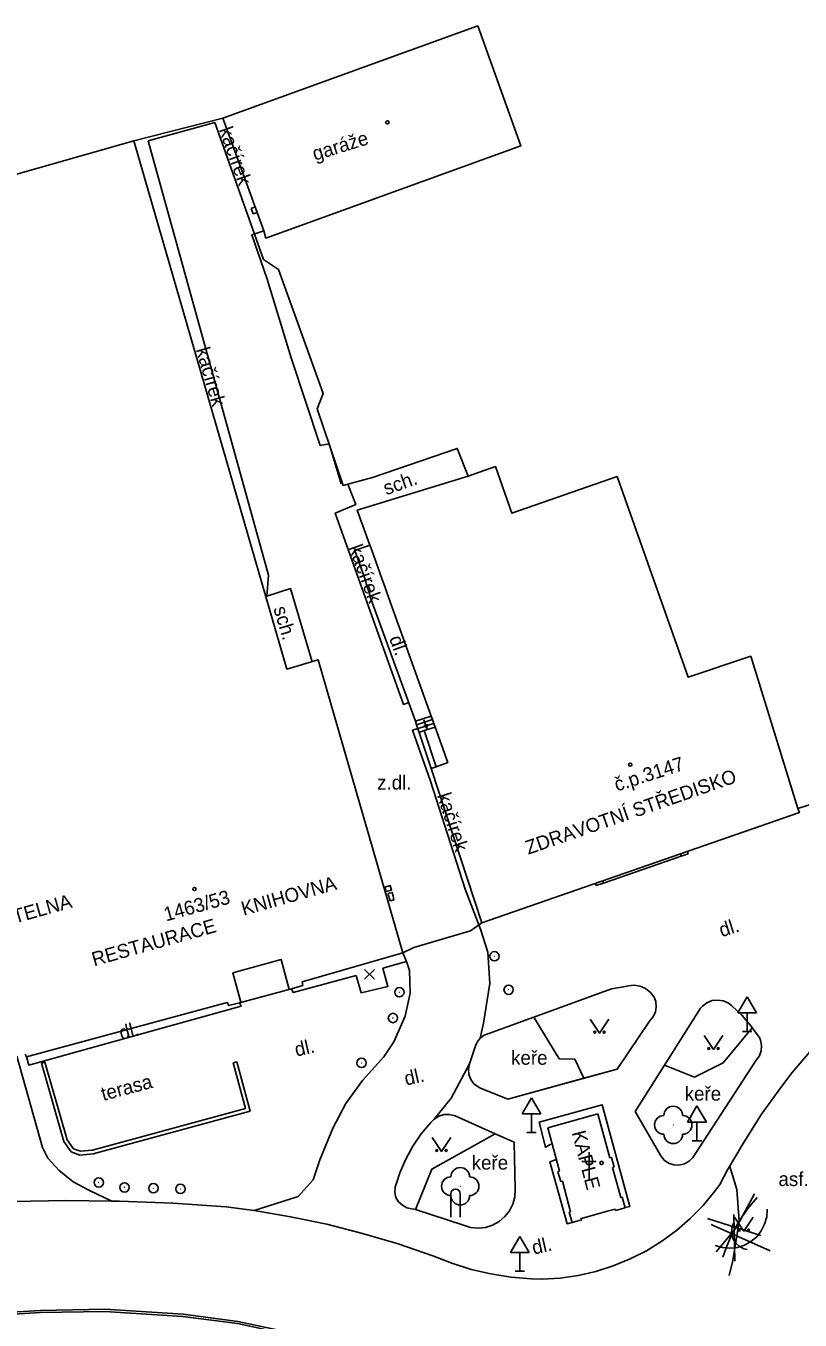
# Model space of a CAD drawing. Extents: x -584400 to -581602, y -1210894 to -1208793.
# Drawn here: x -582919.8 to -582878.3, y -1209481.4 to -1209412.1 of the extents above; entities that cross this region are included whole.
import ezdxf

# ---------------------------------------------------------------- set-up
doc = ezdxf.new("R2010")
doc.units = 0
for name, color, linetype in [('BUDOVY_MĚŘ', 7, 'Continuous'), ('BUDOVY_NEMĚŘ', 7, 'Continuous'), ('OBVOD_PILÍŘE', 7, 'Continuous'), ('POMOC_POPIS', 7, 'Continuous'), ('ROZHRANÍ_PLOCH', 7, 'Continuous'), ('ZELEŇ', 7, 'Continuous'), ('ZN_BUDOV', 7, 'Continuous'), ('ZN_DOPLŇKOVÉ', 7, 'Continuous'), ('ZN_KULTUR', 7, 'Continuous'), ('Č_POPIS_ORIENT', 7, 'Continuous')]:
    doc.layers.add(name, color=color, linetype=linetype)

msp = doc.modelspace()

# ---------------------------------------------------------------- linework, layer by layer
at = {"layer": 'BUDOVY_MĚŘ'}
for points in [[(-582895.57, -1209412.13), (-582909.22, -1209417.06), (-582907.02, -1209423.09), (-582906.91, -1209423.48), (-582893.26, -1209418.55), (-582895.57, -1209412.13)], [(-582913.98, -1209418.28), (-582905.79, -1209446.54), (-582904.11, -1209446.05), (-582899.58, -1209461.71)], [(-582878.44, -1209453.99), (-582878.36, -1209454.21), (-582895.35, -1209460.11), (-582898.06, -1209451.85), (-582897.8, -1209451.76), (-582897.18, -1209451.53), (-582897.86, -1209449.64), (-582897.93, -1209449.44), (-582898, -1209449.24), (-582898.07, -1209449.05), (-582900.42, -1209442.49), (-582900.55, -1209442.12), (-582900.69, -1209441.75), (-582900.82, -1209441.38), (-582901.25, -1209440.18), (-582901.35, -1209439.91), (-582902.02, -1209438.04), (-582896.08, -1209436.22)], [(-582898.06, -1209451.85), (-582897.8, -1209451.76)], [(-582888.84, -1209457.98), (-582884.69, -1209456.54)], [(-582919.72, -1209467.28), (-582908.99, -1209464.37), (-582908.9, -1209464.54), (-582908.32, -1209464.38), (-582905.54, -1209463.64), (-582904.93, -1209463.46), (-582904.97, -1209463.27), (-582899.58, -1209461.71)], [(-582908.25, -1209464.36), (-582908.68, -1209462.78), (-582906.1, -1209462.07), (-582905.67, -1209463.67)], [(-582891.82, -1209471.07), (-582889.15, -1209470.33)], [(-582889.15, -1209470.33), (-582888.5, -1209472.68)], [(-582891.2, -1209473.4), (-582891.82, -1209471.07)], [(-582888.5, -1209472.68), (-582888.42, -1209472.66)], [(-582888.42, -1209472.66), (-582888.28, -1209473.18)], [(-582888.36, -1209473.2), (-582888.28, -1209473.18)], [(-582888.36, -1209473.2), (-582887.91, -1209474.81)], [(-582891.2, -1209473.4), (-582891.28, -1209473.43)], [(-582891.12, -1209473.95), (-582891.28, -1209473.43)], [(-582891.04, -1209473.92), (-582891.12, -1209473.95)], [(-582890.61, -1209475.57), (-582891.04, -1209473.92)], [(-582887.69, -1209475.36), (-582888.2, -1209475.5)], [(-582887.91, -1209474.81), (-582887.84, -1209474.79)], [(-582887.84, -1209474.79), (-582887.69, -1209475.36)], [(-582890.61, -1209475.57), (-582890.69, -1209475.59)], [(-582889.7, -1209475.83), (-582890.04, -1209475.92), (-582890.02, -1209476), (-582890.53, -1209476.14), (-582890.69, -1209475.59)], [(-582890.04, -1209475.92), (-582890.02, -1209476)], [(-582888.22, -1209475.42), (-582888.64, -1209475.53)], [(-582888.22, -1209475.42), (-582888.2, -1209475.5)]]:
    msp.add_lwpolyline(points, dxfattribs=at)
at = {"layer": 'BUDOVY_NEMĚŘ'}
for points in [[(-582913.98, -1209418.28), (-582931.99, -1209423.39), (-582927.85, -1209438.02), (-582922.91, -1209455.53)], [(-582896.08, -1209436.22), (-582894.63, -1209435.7), (-582893.75, -1209438.2), (-582888.12, -1209436.24), (-582884.31, -1209446.97), (-582880.96, -1209445.85), (-582878.44, -1209453.99)], [(-582919.8, -1209467.13), (-582919.72, -1209467.28)]]:
    msp.add_lwpolyline(points, dxfattribs=at)
at = {"layer": 'OBVOD_PILÍŘE'}
for points in [[(-582907.49, -1209421.81), (-582907.7, -1209421.89)], [(-582907.7, -1209421.89), (-582907.65, -1209422.04)], [(-582907.65, -1209422.04), (-582907.59, -1209422.19)], [(-582907.38, -1209422.11), (-582907.49, -1209421.81)], [(-582907.59, -1209422.19), (-582907.38, -1209422.11)], [(-582900.47, -1209458.44), (-582900.54, -1209458.2), (-582900.26, -1209458.12), (-582900.22, -1209458.24), (-582900.19, -1209458.36), (-582900.47, -1209458.44)], [(-582900.38, -1209458.54), (-582900.16, -1209458.48), (-582900.11, -1209458.68), (-582900.06, -1209458.88), (-582900.27, -1209458.93), (-582900.38, -1209458.54)]]:
    msp.add_lwpolyline(points, dxfattribs=at)
at = {"layer": 'ROZHRANÍ_PLOCH'}
for points in [[(-582913.21, -1209418.27), (-582909.65, -1209417.3), (-582907.04, -1209424.62), (-582906.23, -1209425.16), (-582903.84, -1209431.79), (-582904.17, -1209432.61), (-582902.78, -1209436.71), (-582902.53, -1209436.64), (-582902.1, -1209437.74), (-582903.2, -1209438.2), (-582899.55, -1209448.43), (-582899.27, -1209448.33)], [(-582913.21, -1209418.27), (-582906.77, -1209441.51), (-582906.86, -1209442.63), (-582905.59, -1209442.23), (-582904.43, -1209446.14)], [(-582901.35, -1209439.91), (-582902.16, -1209440.19), (-582901.64, -1209441.64)], [(-582901.64, -1209441.64), (-582901.53, -1209442.01)], [(-582901.53, -1209442.01), (-582901.41, -1209442.39)], [(-582901.41, -1209442.39), (-582901.3, -1209442.77)], [(-582901.3, -1209442.77), (-582898.91, -1209449.32)], [(-582898.07, -1209449.05), (-582898.91, -1209449.32), (-582898.85, -1209449.52)], [(-582898.78, -1209449.72), (-582899.06, -1209449.8), (-582898.11, -1209452.54), (-582896.25, -1209458.3), (-582895.42, -1209460.45)], [(-582898.85, -1209449.52), (-582898.42, -1209449.38)], [(-582898.85, -1209449.52), (-582898.78, -1209449.72)], [(-582898.78, -1209449.72), (-582898.41, -1209449.6)], [(-582898.78, -1209449.72), (-582898.71, -1209449.92)], [(-582898.46, -1209449.25), (-582898.42, -1209449.38)], [(-582898.41, -1209449.6), (-582898.46, -1209449.55)], [(-582898.45, -1209449.83), (-582897.86, -1209449.64)], [(-582898.42, -1209449.38), (-582898, -1209449.24)], [(-582898.42, -1209449.38), (-582898.35, -1209449.58)], [(-582898.41, -1209449.6), (-582898.35, -1209449.58)], [(-582898.3, -1209449.71), (-582898.41, -1209449.6)], [(-582898.35, -1209449.58), (-582898.29, -1209449.56)], [(-582898.35, -1209449.58), (-582898.3, -1209449.71)], [(-582898.3, -1209449.71), (-582898.29, -1209449.56)], [(-582898.29, -1209449.56), (-582897.93, -1209449.44)], [(-582898.29, -1209449.56), (-582898.28, -1209449.49)], [(-582898.71, -1209449.92), (-582898.45, -1209449.83)], [(-582898.71, -1209449.92), (-582898.06, -1209451.85)], [(-582898.45, -1209449.83), (-582897.8, -1209451.76)], [(-582884.69, -1209456.54), (-582884.73, -1209456.42)], [(-582884.69, -1209456.54), (-582884.31, -1209456.41)], [(-582884.35, -1209456.29), (-582884.31, -1209456.41)], [(-582889.27, -1209458), (-582889.23, -1209458.11)], [(-582889.23, -1209458.11), (-582888.84, -1209457.98)], [(-582888.84, -1209457.98), (-582888.88, -1209457.86)], [(-582895.42, -1209460.45), (-582895.04, -1209461.67), (-582894.93, -1209463.36), (-582895.26, -1209465.48), (-582895.45, -1209466.28)], [(-582899.39, -1209462.17), (-582899.22, -1209462.66), (-582899.19, -1209463.87), (-582899.46, -1209465.11), (-582900.07, -1209466.48), (-582900.61, -1209467.27), (-582901.75, -1209468.55), (-582902.64, -1209469.77), (-582903.32, -1209471.06), (-582904.02, -1209472.79), (-582904.39, -1209473.86), (-582905.18, -1209474.75), (-582907.54, -1209475.5)], [(-582899.58, -1209461.71), (-582899.39, -1209462.17), (-582900.65, -1209462.53)], [(-582900.65, -1209462.53), (-582900.38, -1209463.51), (-582901.81, -1209463.85), (-582902.08, -1209462.93)], [(-582902.08, -1209462.93), (-582905.46, -1209463.83), (-582905.54, -1209463.64)], [(-582892.58, -1209465.16), (-582888.41, -1209463.64), (-582887.67, -1209463.52)], [(-582886.13, -1209464.08), (-582886.33, -1209463.83), (-582886.59, -1209463.63), (-582886.88, -1209463.5), (-582887.2, -1209463.45), (-582887.52, -1209463.48), (-582887.67, -1209463.52)], [(-582886.39, -1209465.37), (-582886.2, -1209465.15), (-582886.07, -1209464.89), (-582886.02, -1209464.6), (-582886.04, -1209464.31), (-582886.13, -1209464.08)], [(-582880.88, -1209465.72), (-582880.94, -1209465.63), (-582881.44, -1209465.05), (-582882, -1209464.54), (-582882.15, -1209464.41), (-582882.43, -1209464.29), (-582882.73, -1209464.24), (-582883.03, -1209464.27), (-582883.31, -1209464.38), (-582883.55, -1209464.56), (-582883.66, -1209464.68)], [(-582919.72, -1209467.28), (-582919.6, -1209467.72), (-582908.24, -1209464.57), (-582908.32, -1209464.38)], [(-582885.58, -1209467.72), (-582883.66, -1209464.68)], [(-582894.98, -1209466.03), (-582892.58, -1209465.16)], [(-582888.11, -1209467.93), (-582886.39, -1209465.37)], [(-582876.15, -1209465.24), (-582876.58, -1209465.7), (-582877.69, -1209466.89), (-582878.74, -1209468.12), (-582879.36, -1209468.92), (-582880.38, -1209470.35), (-582881.32, -1209471.82), (-582882.2, -1209473.33), (-582882.62, -1209474.1)], [(-582894.98, -1209466.03), (-582895.23, -1209466.12), (-582895.45, -1209466.28), (-582895.61, -1209466.5), (-582895.69, -1209466.69)], [(-582887.15, -1209470.2), (-582885.78, -1209472.58), (-582885.6, -1209472.8), (-582885.36, -1209472.97), (-582885.08, -1209473.06), (-582884.79, -1209473.07), (-582884.51, -1209473), (-582884.26, -1209472.86), (-582884.06, -1209472.66), (-582883.96, -1209472.51), (-582880.67, -1209467.46), (-582880.5, -1209467.23), (-582880.4, -1209466.96), (-582880.38, -1209466.67), (-582880.44, -1209466.39), (-582880.5, -1209466.25), (-582880.88, -1209465.72)], [(-582895.69, -1209466.69), (-582896.01, -1209467.66)], [(-582915.16, -1209475), (-582916.35, -1209474.43), (-582917.22, -1209473.97), (-582917.98, -1209473.36), (-582918.58, -1209472.7), (-582918.87, -1209472.13), (-582920.24, -1209467.25)], [(-582918.93, -1209467.62), (-582918.74, -1209467.57), (-582917.55, -1209471.72), (-582917.21, -1209472.19), (-582916.84, -1209472.33), (-582916.19, -1209472.27), (-582908.01, -1209470.05), (-582908.66, -1209467.6), (-582908.47, -1209467.55)], [(-582918.93, -1209467.62), (-582917.73, -1209471.81), (-582917.34, -1209472.36), (-582916.87, -1209472.53), (-582916.15, -1209472.47), (-582907.76, -1209470.19), (-582908.47, -1209467.55)], [(-582896.01, -1209467.66), (-582896.99, -1209469.48), (-582897.91, -1209470.61)], [(-582896.01, -1209467.66), (-582896.07, -1209467.94), (-582896.05, -1209468.22), (-582895.95, -1209468.49), (-582895.78, -1209468.72), (-582895.55, -1209468.89), (-582895.42, -1209468.95)], [(-582887.15, -1209470.2), (-582885.58, -1209467.72)], [(-582889.89, -1209468.42), (-582893.96, -1209469.55), (-582895.42, -1209468.95)], [(-582888.11, -1209467.93), (-582893.96, -1209469.55)], [(-582888.11, -1209467.93), (-582889.89, -1209468.42)], [(-582893.96, -1209469.55), (-582895.42, -1209468.95)], [(-582896.79, -1209470.44), (-582897.08, -1209470.37), (-582897.37, -1209470.37), (-582897.65, -1209470.45), (-582897.91, -1209470.61)], [(-582896.79, -1209470.44), (-582894.65, -1209471.39)], [(-582887.71, -1209475.34), (-582887.43, -1209475.29), (-582888.92, -1209469.84), (-582892.28, -1209470.77), (-582891.95, -1209472.11), (-582891.66, -1209471.95)], [(-582887.15, -1209470.2), (-582885.78, -1209472.58)], [(-582897.91, -1209470.61), (-582898.08, -1209470.79), (-582898.6, -1209471.4), (-582899.05, -1209472.05), (-582899.43, -1209472.75), (-582899.74, -1209473.49), (-582899.91, -1209473.99), (-582900, -1209474.25), (-582900.02, -1209474.53), (-582899.95, -1209474.8), (-582899.81, -1209475.03), (-582899.61, -1209475.22), (-582899.37, -1209475.35), (-582899.19, -1209475.39), (-582898.9, -1209475.45)], [(-582898.9, -1209475.45), (-582896.34, -1209476.29), (-582895.96, -1209476.4), (-582895.56, -1209476.44), (-582895.16, -1209476.4), (-582894.78, -1209476.28), (-582894.43, -1209476.08), (-582894.12, -1209475.82), (-582893.88, -1209475.51), (-582893.7, -1209475.15), (-582893.59, -1209474.76), (-582893.57, -1209474.34), (-582893.63, -1209471.84)], [(-582894.65, -1209471.39), (-582893.63, -1209471.84)], [(-582885.78, -1209472.58), (-582885.6, -1209472.8), (-582885.36, -1209472.97), (-582885.08, -1209473.06), (-582884.79, -1209473.07), (-582884.51, -1209473), (-582884.26, -1209472.86), (-582884.06, -1209472.66), (-582883.96, -1209472.51)], [(-582891.42, -1209472.79), (-582891.72, -1209472.89), (-582890.78, -1209476.21), (-582890.53, -1209476.14)], [(-582882.08, -1209473.15), (-582881.7, -1209474.37), (-582881.59, -1209476.06), (-582881.92, -1209478.18), (-582882.11, -1209478.98)], [(-582892.14, -1209479.17), (-582891.17, -1209479.11), (-582890.2, -1209478.97), (-582889.25, -1209478.76), (-582888.32, -1209478.46), (-582887.42, -1209478.09), (-582886.55, -1209477.65), (-582885.72, -1209477.14), (-582884.93, -1209476.56), (-582884.2, -1209475.92), (-582883.51, -1209475.23), (-582882.89, -1209474.47), (-582882.62, -1209474.1)], [(-582880.76, -1209474.6), (-582881.74, -1209476.42), (-582882.81, -1209477.7)], [(-582915.16, -1209475), (-582917.6, -1209474.97), (-582920.45, -1209475.01), (-582923.24, -1209475.18)], [(-582897.97, -1209477.92), (-582899.84, -1209477.28), (-582901.74, -1209476.72), (-582903.65, -1209476.23), (-582905.59, -1209475.83), (-582907.54, -1209475.5), (-582909.04, -1209475.3), (-582911.89, -1209475.11), (-582914.74, -1209475), (-582915.16, -1209475)], [(-582880.62, -1209474.8), (-582881.14, -1209475.41), (-582881.59, -1209476.06), (-582881.97, -1209476.76), (-582882.28, -1209477.5), (-582882.45, -1209478)], [(-582883.28, -1209475.93), (-582880.43, -1209476.83)], [(-582882.86, -1209477.37), (-582882.48, -1209477.48), (-582882.08, -1209477.52), (-582881.68, -1209477.48), (-582881.3, -1209477.36), (-582880.95, -1209477.16), (-582880.64, -1209476.9), (-582880.4, -1209476.59), (-582880.22, -1209476.23), (-582880.11, -1209475.84), (-582880.09, -1209475.44), (-582880.09, -1209475.42)], [(-582881.81, -1209478.21), (-582881.87, -1209475.71)], [(-582883.09, -1209476.25), (-582879.93, -1209477.65)], [(-582881.88, -1209476.18), (-582881.97, -1209476.44), (-582881.99, -1209476.72), (-582881.92, -1209476.99), (-582881.78, -1209477.22), (-582881.58, -1209477.41), (-582881.34, -1209477.54), (-582881.16, -1209477.58)], [(-582897.97, -1209477.92), (-582896.96, -1209478.32), (-582895.93, -1209478.65), (-582894.87, -1209478.89), (-582893.8, -1209479.06), (-582892.71, -1209479.15), (-582892.14, -1209479.17)], [(-582929.88, -1209484.26), (-582930.15, -1209483.06), (-582930.12, -1209482.48), (-582929.84, -1209482.11), (-582929.43, -1209481.88), (-582927.43, -1209481.56), (-582923.58, -1209481.11), (-582918.97, -1209480.84), (-582915.54, -1209480.78), (-582911.35, -1209481.04), (-582908.42, -1209481.43), (-582904.61, -1209482.24), (-582901.64, -1209483.05), (-582898.78, -1209484.17), (-582895.2, -1209485.92), (-582892.5, -1209487.49), (-582890.29, -1209489.16), (-582888.57, -1209490.86), (-582887.39, -1209492.22), (-582886.53, -1209493.43)], [(-582929.74, -1209484.35), (-582930.03, -1209483.05), (-582930, -1209482.52), (-582929.76, -1209482.2), (-582929.39, -1209482), (-582927.4, -1209481.68), (-582927.28, -1209481.66), (-582923.57, -1209481.23), (-582918.97, -1209480.96), (-582915.54, -1209480.9), (-582911.36, -1209481.16), (-582908.44, -1209481.55), (-582904.64, -1209482.36), (-582901.68, -1209483.16), (-582898.83, -1209484.28), (-582895.26, -1209486.03), (-582892.57, -1209487.59), (-582890.37, -1209489.25), (-582888.66, -1209490.94), (-582887.48, -1209492.29), (-582886.63, -1209493.5)]]:
    msp.add_lwpolyline(points, dxfattribs=at)
at = {"layer": 'ZELEŇ'}
for points in [[(-582892.58, -1209465.16), (-582891.21, -1209467.39), (-582890.38, -1209467.41), (-582889.89, -1209468.42)], [(-582885.58, -1209467.72), (-582883.97, -1209468.36), (-582882.44, -1209467.6), (-582880.88, -1209465.72)], [(-582898.9, -1209475.45), (-582898.03, -1209473.28), (-582894.65, -1209471.39)]]:
    msp.add_lwpolyline(points, dxfattribs=at)
for centre in [(-582885.11, -1209470.92), (-582896.51, -1209474.2)]:
    msp.add_circle(centre, 0.0005, dxfattribs=at)
for centre, start, end in [((-582885.61, -1209470.92), 89.99999, 269.99999), ((-582885.11, -1209470.42), 0, 179.99999), ((-582884.61, -1209470.92), 270, 89.99999), ((-582885.11, -1209471.42), 179.99999, 359.99999), ((-582896.51, -1209473.7), 0, 179.99999), ((-582897.01, -1209474.2), 89.99999, 269.99999), ((-582896.01, -1209474.2), 270, 89.99999), ((-582896.51, -1209474.7), 179.99999, 359.99999)]:
    msp.add_arc(centre, 0.5, start, end, dxfattribs=at)
at = {"layer": 'ZN_BUDOV'}
for p, q in [((-582901.099, -1209463.129), (-582901.63, -1209462.599)), ((-582901.63, -1209463.129), (-582901.099, -1209462.599)), ((-582889.62, -1209473.87), (-582889.62, -1209472.37)), ((-582889.995, -1209472.87), (-582889.245, -1209472.87))]:
    msp.add_line(p, q, dxfattribs=at)
for centre in [(-582900.41, -1209417.29), (-582887.41, -1209451.65), (-582910.74, -1209458.3), (-582888.95, -1209472.95)]:
    msp.add_circle(centre, 0.0875, dxfattribs=at)
at = {"layer": 'ZN_DOPLŇKOVÉ'}
for p, q in [((-582881.15, -1209464.064), (-582881.65, -1209464.93)), ((-582881.15, -1209464.064), (-582880.65, -1209464.93)), ((-582881.65, -1209464.93), (-582880.65, -1209464.93)), ((-582881.15, -1209465.93), (-582881.15, -1209464.93)), ((-582881.4, -1209465.93), (-582880.9, -1209465.93)), ((-582892.69, -1209469.464), (-582893.19, -1209470.33)), ((-582892.69, -1209469.464), (-582892.19, -1209470.33)), ((-582893.19, -1209470.33), (-582892.19, -1209470.33)), ((-582892.69, -1209471.33), (-582892.69, -1209470.33)), ((-582883.84, -1209469.904), (-582884.34, -1209470.77)), ((-582883.84, -1209469.904), (-582883.34, -1209470.77)), ((-582884.34, -1209470.77), (-582883.34, -1209470.77)), ((-582883.84, -1209471.77), (-582883.84, -1209470.77)), ((-582892.94, -1209471.33), (-582892.44, -1209471.33)), ((-582884.09, -1209471.77), (-582883.59, -1209471.77)), ((-582897.01, -1209475.85), (-582897.01, -1209474.6)), ((-582896.51, -1209475.85), (-582896.51, -1209474.6)), ((-582893.33, -1209476.884), (-582893.83, -1209477.75)), ((-582893.33, -1209476.884), (-582892.83, -1209477.75)), ((-582893.83, -1209477.75), (-582892.83, -1209477.75)), ((-582893.33, -1209478.75), (-582893.33, -1209477.75)), ((-582893.58, -1209478.75), (-582893.08, -1209478.75))]:
    msp.add_line(p, q, dxfattribs=at)
for points in [[(-582913.98, -1209418.28), (-582909.22, -1209417.06)], [(-582907.02, -1209423.09), (-582907.66, -1209423.31), (-582906.84, -1209425.67)], [(-582906.84, -1209425.67), (-582905.56, -1209429.89)], [(-582905.56, -1209429.89), (-582904, -1209434.58), (-582903.52, -1209434.49), (-582902.89, -1209436.62)], [(-582902.53, -1209436.64), (-582901.2, -1209436.28), (-582896.67, -1209434.73), (-582896.08, -1209436.22)], [(-582906.86, -1209442.63), (-582905.59, -1209442.23), (-582904.43, -1209446.14)], [(-582878.44, -1209453.99), (-582874.45, -1209452.71)], [(-582895.35, -1209460.11), (-582895.97, -1209460.53)], [(-582895.97, -1209460.53), (-582899, -1209461.43)], [(-582899, -1209461.43), (-582899.58, -1209461.71)], [(-582889.7, -1209475.83), (-582888.64, -1209475.53)]]:
    msp.add_lwpolyline(points, dxfattribs=at)
for centre, radius in [((-582894.681, -1209461.9), 0.25), ((-582894.681, -1209461.9), 0.0005), ((-582899.77, -1209463.82), 0.25), ((-582893.921, -1209463.69), 0.25), ((-582899.77, -1209463.82), 0.0005), ((-582893.921, -1209463.69), 0.0005), ((-582900.111, -1209465.2), 0.25), ((-582900.111, -1209465.2), 0.0005), ((-582901.791, -1209467.6), 0.25), ((-582901.791, -1209467.6), 0.0005), ((-582915.861, -1209474), 0.25), ((-582915.861, -1209474), 0.0005), ((-582914.481, -1209474.26), 0.25), ((-582914.481, -1209474.26), 0.0005), ((-582912.931, -1209474.31), 0.25), ((-582912.931, -1209474.31), 0.0005), ((-582911.49, -1209474.34), 0.25), ((-582911.49, -1209474.34), 0.0005)]:
    msp.add_circle(centre, radius, dxfattribs=at)
msp.add_arc((-582896.76, -1209474.6), 0.25, 0, 179.99999, dxfattribs=at)
at = {"layer": 'ZN_KULTUR'}
for points in [[(-582889.56, -1209465.26), (-582889.06, -1209466.01), (-582888.56, -1209465.26)], [(-582883.46, -1209466.13), (-582882.96, -1209466.88), (-582882.46, -1209466.13)], [(-582898.02, -1209471.59), (-582897.52, -1209472.34), (-582897.02, -1209471.59)], [(-582881.83, -1209475.85), (-582881.33, -1209476.6), (-582880.83, -1209475.85)]]:
    msp.add_lwpolyline(points, dxfattribs=at)
for centre in [(-582889.31, -1209465.96), (-582888.81, -1209465.96), (-582883.21, -1209466.83), (-582882.71, -1209466.83), (-582897.77, -1209472.29), (-582897.27, -1209472.29), (-582881.58, -1209476.55), (-582881.08, -1209476.55)]:
    msp.add_circle(centre, 0.05, dxfattribs=at)

# ---------------------------------------------------------------- texts
at = {"layer": 'POMOC_POPIS'}
for s, rotation, p in [('kačírek', 289.62409, (-582909.44, -1209417.68)), ('garáže', 17.137, (-582904.29, -1209419.35)), ('kačírek', 286.16205, (-582910.67, -1209429.44)), ('sch.', 19.61298, (-582900.47, -1209437.24)), ('kačírek', 290.0463, (-582902.49, -1209440.03)), ('sch.', 286.86702, (-582906.52, -1209443.29)), ('dl.', 290.0463, (-582900.33, -1209444.89)), ('ZDRAVOTNÍ STŘEDISKO', 19.151, (-582892.87, -1209456.47)), ('kačírek', 287.89611, (-582897.76, -1209453.29)), ('KNIHOVNA', 15.67899, (-582908.11, -1209459.73)), ('ČESKÁ SPOŘITELNA', 15.67916, (-582926.89, -1209461.99)), ('RESTAURACE', 15.67899, (-582916.11, -1209462.44)), ('dl.', 17.60401, (-582882.52, -1209460.88)), ('dl.', 14.38703, (-582914.66, -1209466.38)), ('dl.', 12.96099, (-582905.28, -1209467.27)), ('terasa', 14.93002, (-582915.62, -1209469.64)), ('dl.', 12.96099, (-582899.41, -1209468.82)), ('KAPLE', 284.78798, (-582890.55, -1209471.33)), ('dl.', 12.96099, (-582892.58, -1209477.86))]:
    msp.add_text(s, height=0.75, rotation=rotation, dxfattribs=at).set_placement(p)
for s, p in [('z.dl.', (-582900.96, -1209452.98)), ('asf.', (-582879.48, -1209474.19))]:
    msp.add_text(s, height=0.75, dxfattribs=at).set_placement(p)
at = {"layer": 'ZELEŇ'}
for p in [(-582893.79, -1209467.7), (-582884.5, -1209469.62), (-582895.9, -1209473.31)]:
    msp.add_text('keře', height=0.75, dxfattribs=at).set_placement(p)
at = {"layer": 'Č_POPIS_ORIENT'}
for s, rotation, p in [('č.p.3147', 17.80002, (-582888.13, -1209453.09)), ('1463/53', 15.68002, (-582912.26, -1209460.04))]:
    msp.add_text(s, height=0.75, rotation=rotation, dxfattribs=at).set_placement(p)

doc.saveas('drawing.dxf')
